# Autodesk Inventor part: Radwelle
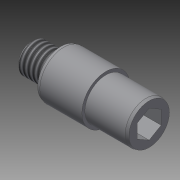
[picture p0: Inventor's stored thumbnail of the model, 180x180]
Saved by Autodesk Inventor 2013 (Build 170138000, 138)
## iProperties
Created: 2012-07
Part Number: Radwelle
Material: Allgemein
Document SubType Name: Modeling
Designer: rYan
Density: 1 g/cm^3
Mass: 0.839271 g
Surface Area: 5.9972 cm^2
Volume: 0.839271 cm^3
Author: rYan
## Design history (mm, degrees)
revolve "Umdrehung1" stored, may be unused: angle "d7" = 90 deg
sketch "Skizze2"
  geometry: L1 (1.155, 2)-(2.309, 0); L2 (2.309, 0)-(1.155, -2); L3 (1.155, -2)-(-1.155, -2); L4 (-1.155, -2)-(-2.309, 0); L5 (-2.309, 0)-(-1.155, 2); L6 (-1.155, 2)-(1.155, 2); L7 (-4.9, 0)-(4.9, 0); C1 r 3.5 at (0, 0) reference; 2 further points
  constraints: 14 end point, 1 coincident, 1 parallel, 13 other
  dimensions: "d8" = 4 distance between parallel lines of L3 L6
extrude "Extrusion1" cut sketch "Skizze2" distance "d9" = 3; taper "d10" = 0 deg
feature "Gewinde1" dims "d11" = 3.5, "d12" = 0
chamfer "Fase1" distance "d13" = 0.5; stored, may be unused: second distance "d14" = 2, angle "d15" = 15 deg
chamfer "Fase2" distance "d16" = 0.5; stored, may be unused: second distance "d17" = 2, angle "d18" = 45 deg
chamfer "Fase3" distance "d21" = 0.5; stored, may be unused: second distance "d22" = 2, angle "d23" = 15 deg
node "Volumenkörper1"
sketch "Skizze1"
  geometry: L1 (0, 0)-(0, 2.5); L2 (0, 2.5)-(5, 2.5); L3 (5, 2.5)-(5, 4); L4 (5, 4)-(12.5, 4); L5 (19.7, 3.5)-(19.7, 0); L6 (19.7, 0)-(0, 0); L7 (12.5, 4)-(12.5, 3.5); L8 (12.5, 3.5)-(19.7, 3.5); L9 (19.7, 3.5)-(19.7, 0)
  constraints: 18 end point, 4 parallel, 3 perpendicular, 1 collinear, 1 vertical
  dimensions: "d0" = 19.7 distance between parallel lines of L5 L1; "d2" = 5 diameter of L2 L6; "d3" = 8 diameter of L4 L6; "d4" = 5 distance between parallel lines of L1 L3; "d19" = 7 diameter of L8 L6; "d20" = 7.2 distance between parallel lines of L5 L7
